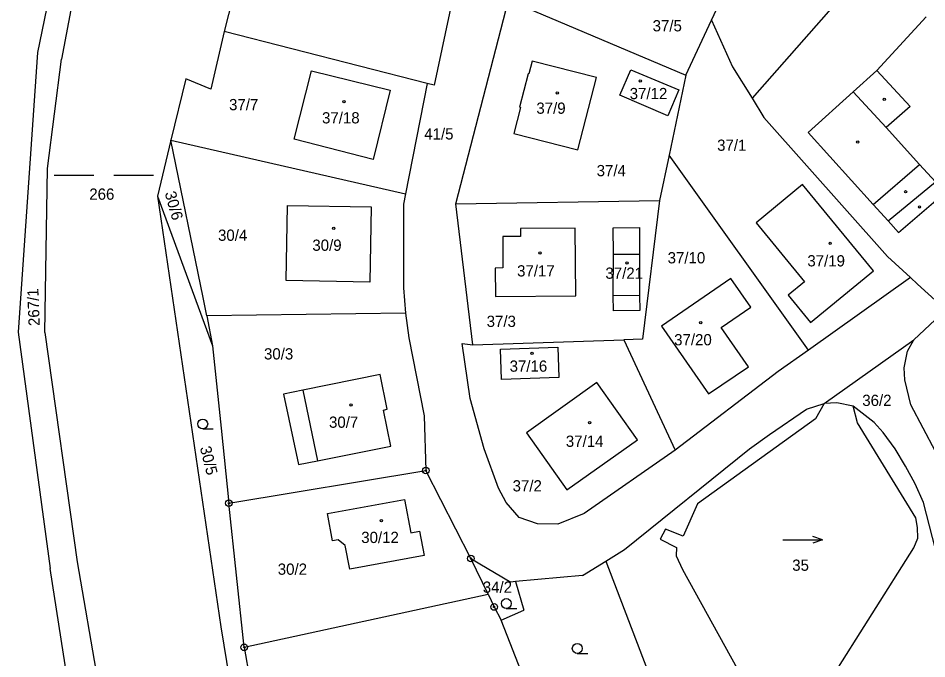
# Model space of a CAD drawing. Extents: x -762263 to -760336, y -1154405 to -1152076.
# Drawn here: x -761833.7 to -761696.3, y -1152440.5 to -1152343.6 of the extents above; entities that cross this region are included whole.
import ezdxf

# ---------------------------------------------------------------- set-up
doc = ezdxf.new("R2010")
doc.units = 0
for name, color, linetype in [('Vrstva 1', 7, 'Continuous'), ('Vrstva 18', 7, 'Continuous'), ('Vrstva 19', 7, 'Continuous'), ('Vrstva 24', 7, 'Continuous'), ('Vrstva 25', 7, 'Continuous'), ('Vrstva 4', 7, 'Continuous')]:
    doc.layers.add(name, color=color, linetype=linetype)

msp = doc.modelspace()

# ---------------------------------------------------------------- linework, layer by layer
at = {"layer": 'Vrstva 1'}
for p, q in [((-761795.26, -1152316.98), (-761802.58, -1152345.63)), ((-761825.79, -1152324.72), (-761830.82, -1152348.81)), ((-761822.59, -1152325.61), (-761827.15, -1152349.83)), ((-761728.86, -1152343.91), (-761723.87, -1152333.22)), ((-761705.66, -1152336.28), (-761722.74, -1152355.74)), ((-761767.6, -1152338.7), (-761770.81, -1152353.77)), ((-761767.56, -1152371.68), (-761759.59, -1152340.87)), ((-761759.59, -1152340.87), (-761732.75, -1152352.26)), ((-761732.75, -1152352.26), (-761728.86, -1152343.91)), ((-761728.86, -1152343.91), (-761725.72, -1152350.98)), ((-761703.88, -1152351.54), (-761696.41, -1152343.42)), ((-761802.58, -1152345.63), (-761804.57, -1152354.36)), ((-761771.89, -1152353.48), (-761802.58, -1152345.63)), ((-761830.82, -1152348.81), (-761833.72, -1152391.11)), ((-761829.29, -1152366.37), (-761827.15, -1152349.83)), ((-761755.98, -1152350.12), (-761756.48, -1152352.05)), ((-761746.27, -1152352.59), (-761755.98, -1152350.12)), ((-761742.73, -1152355.27), (-761741.08, -1152351.42)), ((-761741.08, -1152351.42), (-761733.81, -1152354.48)), ((-761725.72, -1152350.98), (-761722.74, -1152355.74)), ((-761808.37, -1152352.81), (-761810.61, -1152362.08)), ((-761804.57, -1152354.36), (-761808.37, -1152352.81)), ((-761791.96, -1152361.94), (-761789.36, -1152351.58)), ((-761789.36, -1152351.58), (-761777.45, -1152354.53)), ((-761756.62, -1152352.02), (-761757.92, -1152357.09)), ((-761756.48, -1152352.05), (-761756.62, -1152352.02)), ((-761749.07, -1152363.53), (-761746.27, -1152352.59)), ((-761732.75, -1152352.26), (-761735.28, -1152364.35)), ((-761703.88, -1152351.54), (-761707.43, -1152354.74)), ((-761771.89, -1152353.48), (-761775.16, -1152370.16)), ((-761770.81, -1152353.77), (-761771.89, -1152353.48)), ((-761777.45, -1152354.53), (-761780.04, -1152364.99)), ((-761735.5, -1152358.39), (-761742.73, -1152355.27)), ((-761733.81, -1152354.48), (-761735.5, -1152358.39)), ((-761707.43, -1152354.74), (-761714.28, -1152360.93)), ((-761722.74, -1152355.74), (-761720.94, -1152358.62)), ((-761757.78, -1152357.13), (-761758.78, -1152361.04)), ((-761757.92, -1152357.09), (-761757.78, -1152357.13)), ((-761702.26, -1152379.67), (-761720.94, -1152358.62)), ((-761758.78, -1152361.04), (-761749.07, -1152363.53)), ((-761704.43, -1152371.78), (-761714.28, -1152360.93)), ((-761810.61, -1152362.08), (-761812.66, -1152370.55)), ((-761805.72, -1152385.88), (-761810.61, -1152362.08)), ((-761810.61, -1152362.08), (-761775.16, -1152370.16)), ((-761780.04, -1152364.99), (-761791.96, -1152361.94)), ((-761735.28, -1152364.35), (-761736.75, -1152371.2)), ((-761714.19, -1152393.8), (-761735.28, -1152364.35)), ((-761829.67, -1152391.16), (-761829.29, -1152366.37)), ((-761715.11, -1152368.75), (-761722.12, -1152374.56)), ((-761704.39, -1152381.84), (-761715.11, -1152368.75)), ((-761812.66, -1152370.55), (-761804.33, -1152393.16)), ((-761812.66, -1152370.55), (-761803.06, -1152435.66)), ((-761775.16, -1152370.16), (-761775.47, -1152371.77)), ((-761700.58, -1152376.01), (-761693.55, -1152370)), ((-761793.18, -1152383.3), (-761793, -1152371.96)), ((-761793, -1152371.96), (-761780.36, -1152372.17)), ((-761775.47, -1152371.77), (-761775.45, -1152384.42)), ((-761767.56, -1152371.68), (-761736.75, -1152371.2)), ((-761764.99, -1152393.03), (-761767.56, -1152371.68)), ((-761736.75, -1152371.2), (-761739.33, -1152392.15)), ((-761702.15, -1152374.28), (-761704.43, -1152371.78)), ((-761780.36, -1152372.17), (-761780.54, -1152383.53)), ((-761722.12, -1152374.56), (-761714.81, -1152383.47)), ((-761700.58, -1152376.01), (-761702.15, -1152374.28)), ((-761749.47, -1152375.36), (-761757.77, -1152375.44)), ((-761757.77, -1152375.44), (-761757.76, -1152376.64)), ((-761749.4, -1152385.6), (-761749.47, -1152375.36)), ((-761743.73, -1152375.3), (-761739.78, -1152375.27)), ((-761743.69, -1152379.33), (-761743.73, -1152375.3)), ((-761739.78, -1152375.27), (-761739.74, -1152379.29)), ((-761757.76, -1152376.64), (-761760.44, -1152376.65)), ((-761760.44, -1152376.65), (-761760.41, -1152381.39)), ((-761743.72, -1152385.54), (-761743.69, -1152379.33)), ((-761739.74, -1152379.29), (-761739.75, -1152385.5)), ((-761702.26, -1152379.67), (-761698.8, -1152382.84)), ((-761760.41, -1152381.39), (-761761.61, -1152381.41)), ((-761761.61, -1152381.41), (-761761.56, -1152385.72)), ((-761725.95, -1152382.97), (-761736.45, -1152390.17)), ((-761722.93, -1152387.3), (-761725.95, -1152382.97)), ((-761698.8, -1152382.84), (-761714.19, -1152393.8)), ((-761713.9, -1152389.62), (-761704.39, -1152381.84)), ((-761698.8, -1152382.84), (-761697.7, -1152383.84)), ((-761780.54, -1152383.53), (-761793.18, -1152383.3)), ((-761775.45, -1152384.42), (-761775.17, -1152388.22)), ((-761714.81, -1152383.47), (-761717.29, -1152385.49)), ((-761697.7, -1152383.84), (-761693.44, -1152387.74)), ((-761761.56, -1152385.72), (-761749.4, -1152385.6)), ((-761743.7, -1152387.85), (-761743.72, -1152385.54)), ((-761739.75, -1152385.5), (-761739.73, -1152387.81)), ((-761717.29, -1152385.49), (-761713.9, -1152389.62)), ((-761805.2, -1152388.62), (-761805.72, -1152385.88)), ((-761775.17, -1152388.22), (-761805.2, -1152388.62)), ((-761775.17, -1152388.22), (-761774.66, -1152391.96)), ((-761739.73, -1152387.81), (-761743.7, -1152387.85)), ((-761727.41, -1152390.38), (-761722.93, -1152387.3)), ((-761698.3, -1152392.27), (-761693.44, -1152387.74)), ((-761805.2, -1152388.62), (-761804.33, -1152393.16)), ((-761833.72, -1152391.11), (-761828.88, -1152426.85)), ((-761829.67, -1152391.16), (-761824.8, -1152425.85)), ((-761736.45, -1152390.17), (-761729.34, -1152400.42)), ((-761723.3, -1152396.33), (-761727.41, -1152390.38)), ((-761774.66, -1152391.96), (-761772.34, -1152403.73)), ((-761764.99, -1152393.03), (-761742.15, -1152392.25)), ((-761739.33, -1152392.15), (-761742.15, -1152392.25)), ((-761742.15, -1152392.25), (-761734.38, -1152408.95)), ((-761711.82, -1152401.88), (-761698.3, -1152392.27)), ((-761699.26, -1152393.96), (-761698.3, -1152392.27)), ((-761804.33, -1152393.16), (-761803.03, -1152405.59)), ((-761765.36, -1152401.11), (-761766.57, -1152392.83)), ((-761766.57, -1152392.83), (-761764.99, -1152393.03)), ((-761760.8, -1152393.69), (-761752.13, -1152393.39)), ((-761760.64, -1152398.25), (-761760.8, -1152393.69)), ((-761752.13, -1152393.39), (-761751.96, -1152397.94)), ((-761714.19, -1152393.8), (-761718.77, -1152397.05)), ((-761699.75, -1152396.47), (-761699.26, -1152393.96)), ((-761729.34, -1152400.42), (-761723.3, -1152396.33)), ((-761699.64, -1152398.32), (-761699.75, -1152396.47)), ((-761778.98, -1152397.51), (-761790.68, -1152399.88)), ((-761777.92, -1152402.75), (-761778.98, -1152397.51)), ((-761751.96, -1152397.94), (-761760.64, -1152398.25)), ((-761718.77, -1152397.05), (-761734.38, -1152408.95)), ((-761746.22, -1152398.73), (-761756.87, -1152406.33)), ((-761740.04, -1152407.39), (-761746.22, -1152398.73)), ((-761698.72, -1152402.07), (-761699.64, -1152398.32)), ((-761790.68, -1152399.88), (-761793.59, -1152400.45)), ((-761793.59, -1152400.45), (-761791.34, -1152411.1)), ((-761763.26, -1152408.73), (-761765.36, -1152401.11)), ((-761714.51, -1152402.76), (-761711.82, -1152401.88)), ((-761711.82, -1152401.88), (-761713.15, -1152404.22)), ((-761709.9, -1152401.76), (-761711.82, -1152401.88)), ((-761707.45, -1152402.27), (-761709.9, -1152401.76)), ((-761706.8, -1152404.83), (-761707.45, -1152402.27)), ((-761704.27, -1152404.74), (-761707.45, -1152402.27)), ((-761692.11, -1152414.68), (-761698.72, -1152402.07)), ((-761778.45, -1152402.89), (-761777.92, -1152402.75)), ((-761777.38, -1152408.34), (-761778.45, -1152402.89)), ((-761720.08, -1152406.57), (-761714.51, -1152402.76)), ((-761772.34, -1152403.73), (-761772.07, -1152412)), ((-761713.15, -1152404.22), (-761730.98, -1152417.04)), ((-761698, -1152419.19), (-761706.8, -1152404.83)), ((-761702.94, -1152406.29), (-761704.27, -1152404.74)), ((-761803.03, -1152405.59), (-761801.85, -1152416.94)), ((-761756.87, -1152406.33), (-761750.73, -1152414.94)), ((-761701.1, -1152408.74), (-761702.94, -1152406.29)), ((-761750.73, -1152414.94), (-761740.04, -1152407.39)), ((-761723.11, -1152408.74), (-761720.08, -1152406.57)), ((-761788.46, -1152410.56), (-761777.38, -1152408.34)), ((-761761.06, -1152414.67), (-761763.26, -1152408.73)), ((-761734.38, -1152408.95), (-761748.15, -1152418.5)), ((-761742.05, -1152423.98), (-761723.11, -1152408.74)), ((-761699.52, -1152411.37), (-761701.1, -1152408.74)), ((-761791.34, -1152411.1), (-761788.46, -1152410.56)), ((-761698.07, -1152414.04), (-761699.52, -1152411.37)), ((-761801.85, -1152416.94), (-761772.07, -1152412)), ((-761765.26, -1152425.32), (-761772.07, -1152412)), ((-761759.93, -1152416.85), (-761761.06, -1152414.67)), ((-761696.82, -1152416.83), (-761698.07, -1152414.04)), ((-761799.54, -1152438.75), (-761801.85, -1152416.94)), ((-761786.95, -1152418.53), (-761775.32, -1152416.38)), ((-761775.32, -1152416.38), (-761774.36, -1152421.44)), ((-761757.96, -1152419.11), (-761759.93, -1152416.85)), ((-761730.98, -1152417.04), (-761733.15, -1152421.95)), ((-761688.93, -1152447.74), (-761696.82, -1152416.83)), ((-761786.18, -1152422.65), (-761786.95, -1152418.53)), ((-761748.15, -1152418.5), (-761752.12, -1152420.11)), ((-761755.18, -1152420.1), (-761757.96, -1152419.11)), ((-761752.12, -1152420.11), (-761755.18, -1152420.1)), ((-761697.72, -1152420.61), (-761698, -1152419.19)), ((-761774.36, -1152421.44), (-761773.01, -1152421.21)), ((-761773.01, -1152421.21), (-761772.34, -1152424.88)), ((-761735.85, -1152420.88), (-761736.62, -1152422.42)), ((-761733.15, -1152421.95), (-761735.85, -1152420.88)), ((-761697.66, -1152422.23), (-761697.72, -1152420.61)), ((-761785.32, -1152422.5), (-761786.18, -1152422.65)), ((-761784.25, -1152423.38), (-761785.32, -1152422.5)), ((-761736.62, -1152422.42), (-761734.18, -1152423.64)), ((-761698.3, -1152423.7), (-761697.66, -1152422.23)), ((-761783.57, -1152426.95), (-761784.25, -1152423.38)), ((-761744.84, -1152425.71), (-761742.05, -1152423.98)), ((-761734.18, -1152423.64), (-761734.21, -1152424.92)), ((-761714.06, -1152448.71), (-761698.3, -1152423.7)), ((-761772.34, -1152424.88), (-761783.57, -1152426.95)), ((-761762.66, -1152430.71), (-761765.26, -1152425.32)), ((-761765.26, -1152425.32), (-761759.2, -1152428.88)), ((-761734.21, -1152424.92), (-761733.27, -1152426.99)), ((-761817.78, -1152498.33), (-761828.88, -1152426.85)), ((-761824.8, -1152425.85), (-761819.79, -1152454.71)), ((-761748.39, -1152427.91), (-761744.84, -1152425.71)), ((-761744.84, -1152425.71), (-761735.7, -1152449.59)), ((-761733.27, -1152426.99), (-761724.98, -1152441.93)), ((-761748.39, -1152427.91), (-761758.51, -1152428.82)), ((-761758.51, -1152428.82), (-761759.2, -1152428.88)), ((-761758.51, -1152428.82), (-761757.24, -1152433.14)), ((-761799.54, -1152438.75), (-761762.66, -1152430.71)), ((-761762.66, -1152430.71), (-761761.75, -1152432.65)), ((-761761.75, -1152432.65), (-761760.7, -1152434.65)), ((-761760.7, -1152434.65), (-761757.24, -1152433.14)), ((-761754.51, -1152450.42), (-761760.7, -1152434.65)), ((-761803.06, -1152435.66), (-761796.61, -1152474.71)), ((-761799.54, -1152438.75), (-761793.55, -1152473.48))]:
    msp.add_line(p, q, dxfattribs=at)
at = {"layer": 'Vrstva 24'}
for centre, radius in [((-761772.07, -1152412), 0.5), ((-761772.07, -1152412), 0.1), ((-761801.85, -1152416.94), 0.5), ((-761801.85, -1152416.94), 0.1), ((-761765.26, -1152425.32), 0.5), ((-761765.26, -1152425.32), 0.1), ((-761761.75, -1152432.65), 0.5), ((-761761.75, -1152432.65), 0.1), ((-761799.54, -1152438.75), 0.5), ((-761799.54, -1152438.75), 0.1)]:
    msp.add_circle(centre, radius, dxfattribs=at)
at = {"layer": 'Vrstva 25'}
for p, q in [((-761828.26, -1152367.34), (-761822.26, -1152367.34)), ((-761819.26, -1152367.34), (-761813.26, -1152367.34)), ((-761805.81, -1152405.73), (-761804.21, -1152405.73)), ((-761759.9, -1152432.88), (-761758.3, -1152432.88)), ((-761749.17, -1152439.67), (-761747.57, -1152439.67))]:
    msp.add_line(p, q, dxfattribs=at)
for points in [[(-761718.07, -1152422.5), (-761712.07, -1152422.5), (-761713.57, -1152422)], [(-761712.07, -1152422.5), (-761713.57, -1152423)]]:
    msp.add_lwpolyline(points, dxfattribs=at)
for centre, radius in [((-761739.65, -1152353.11), 0.175), ((-761752.2, -1152354.92), 0.175), ((-761784.45, -1152356.24), 0.175), ((-761702.74, -1152355.89), 0.175), ((-761706.76, -1152362.36), 0.175), ((-761699.52, -1152369.88), 0.175), ((-761697.42, -1152372.17), 0.175), ((-761786.01, -1152375.4), 0.175), ((-761710.93, -1152377.66), 0.175), ((-761754.81, -1152379.12), 0.175), ((-761741.65, -1152380.63), 0.175), ((-761730.49, -1152389.67), 0.175), ((-761756, -1152394.32), 0.175), ((-761783.37, -1152402.09), 0.175), ((-761805.81, -1152404.98), 0.75), ((-761747.32, -1152404.8), 0.175), ((-761778.78, -1152419.58), 0.175), ((-761759.9, -1152432.13), 0.75), ((-761749.17, -1152438.92), 0.75)]:
    msp.add_circle(centre, radius, dxfattribs=at)
at = {"layer": 'Vrstva 4'}
for p, q in [((-761703.88, -1152351.54), (-761698.81, -1152356.96)), ((-761707.43, -1152354.74), (-761702.45, -1152360.14)), ((-761698.81, -1152356.96), (-761702.45, -1152360.14)), ((-761702.45, -1152360.14), (-761697.4, -1152365.74)), ((-761704.43, -1152371.78), (-761697.4, -1152365.74)), ((-761697.4, -1152365.74), (-761695.02, -1152368.37)), ((-761702.15, -1152374.28), (-761695.02, -1152368.37)), ((-761743.69, -1152379.33), (-761739.74, -1152379.29)), ((-761743.72, -1152385.54), (-761739.75, -1152385.5)), ((-761790.68, -1152399.88), (-761788.46, -1152410.56))]:
    msp.add_line(p, q, dxfattribs=at)

# ---------------------------------------------------------------- texts
at = {"layer": 'Vrstva 18'}
for s, p in [('37/5', (-761737.778, -1152345.62)), ('37/7', (-761801.831, -1152357.54)), ('41/5', (-761772.313, -1152361.97)), ('37/1', (-761728.023, -1152363.68)), ('37/4', (-761746.241, -1152367.52)), ('266', (-761822.968, -1152371.08)), ('30/4', (-761803.498, -1152377.29)), ('37/10', (-761735.509, -1152380.7)), ('37/3', (-761762.878, -1152390.31)), ('30/3', (-761796.545, -1152395.23)), ('36/2', (-761706.075, -1152402.26)), ('37/2', (-761758.954, -1152415.18)), ('35', (-761716.669, -1152427.18)), ('30/2', (-761794.463, -1152427.78)), ('34/2', (-761763.455, -1152430.5))]:
    msp.add_text(s, height=1.7, dxfattribs=at).set_placement(p)
for s, rotation, p in [('30/6', 285.73405, (-761811.575, -1152370.059)), ('267/1', 92.3035, (-761830.445, -1152390.136)), ('30/5', 284.35895, (-761806.261, -1152408.56))]:
    msp.add_text(s, height=1.7, rotation=rotation, dxfattribs=at).set_placement(p)
at = {"layer": 'Vrstva 19'}
for s, p in [('37/12', (-761741.246, -1152355.87)), ('37/9', (-761755.361, -1152358.08)), ('37/18', (-761787.772, -1152359.54)), ('30/9', (-761789.238, -1152378.8)), ('37/19', (-761714.382, -1152381.16)), ('37/17', (-761758.272, -1152382.68)), ('37/21', (-761744.916, -1152383.03)), ('37/20', (-761734.52, -1152393.09)), ('37/16', (-761759.402, -1152397.08)), ('30/7', (-761786.717, -1152405.56)), ('37/14', (-761750.902, -1152408.44)), ('30/12', (-761781.843, -1152422.98))]:
    msp.add_text(s, height=1.7, dxfattribs=at).set_placement(p)

doc.saveas('drawing.dxf')
